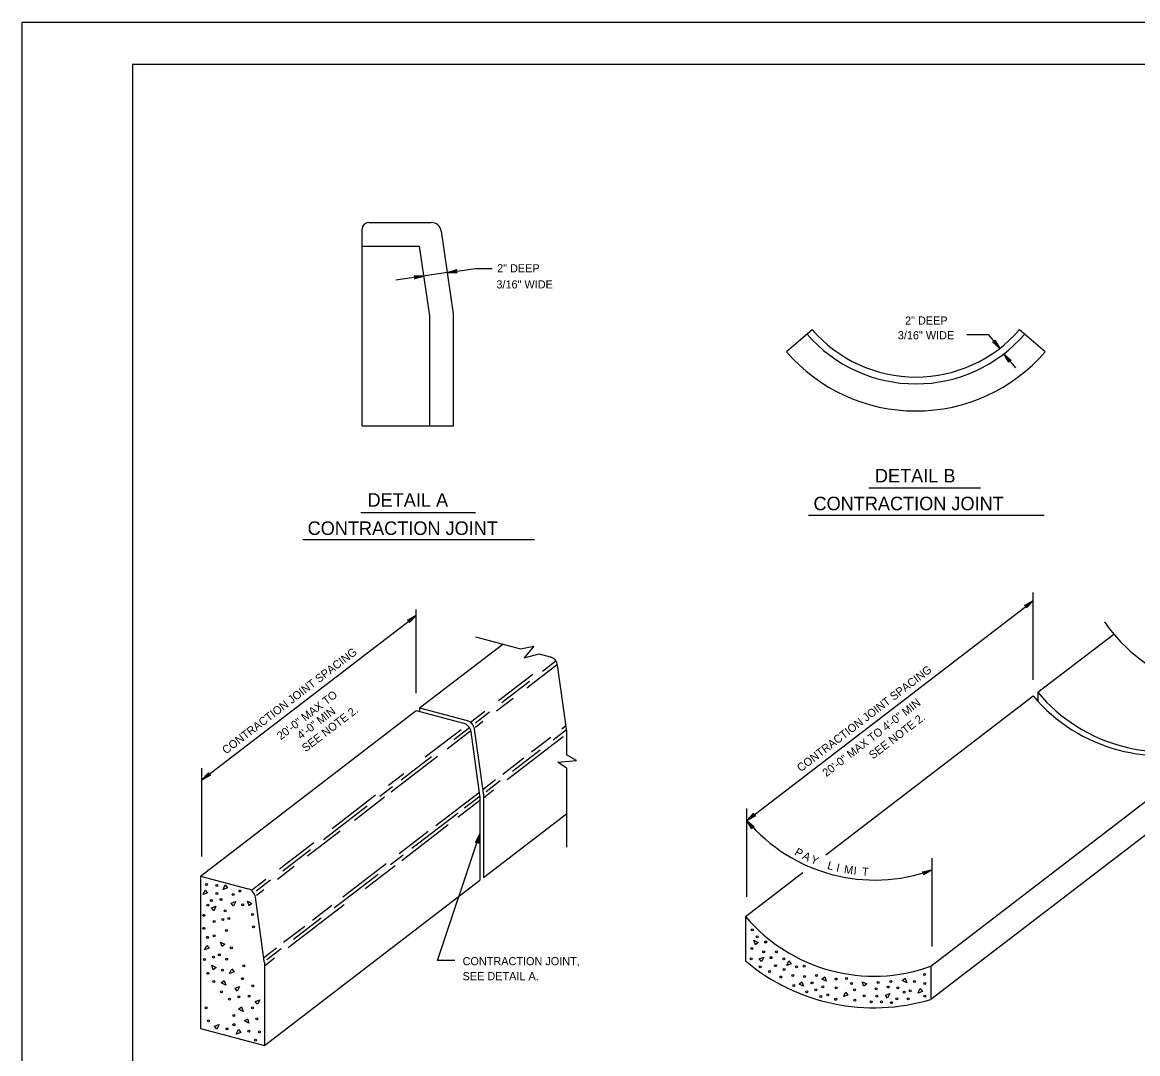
# Model space of a CAD drawing. Extents: x 2092490 to 2102560, y 980575 to 982524.
# Drawn here: x 2096834 to 2098130, y 981325 to 982524 of the extents above; entities that cross this region are included whole.
import ezdxf

# ---------------------------------------------------------------- set-up
doc = ezdxf.new("R2010")
doc.units = 0
for name, color, linetype in [('1', 7, 'Continuous'), ('2', 7, 'Continuous'), ('3', 7, 'Continuous'), ('57', 7, 'Continuous'), ('PLT-BNDY', 7, 'Continuous')]:
    doc.layers.add(name, color=color, linetype=linetype)

msp = doc.modelspace()

# ---------------------------------------------------------------- linework, layer by layer
at = {"layer": '1'}
for p, q in [((2099540.8, 982474.5), (2096962.1, 982474.5)), ((2096962.1, 982474.5), (2096962.1, 980624.1)), ((2097752, 982166.4), (2097722.2, 982140.7)), ((2098022.9, 982140.7), (2097993.1, 982166.4))]:
    msp.add_line(p, q, dxfattribs=at)
for radius in [167.3, 159.4, 198.8]:
    msp.add_arc((2097872.6, 982270.8), radius, 220.8681, 319.1319, dxfattribs=at)
at = {"layer": '2'}
for p, q in [((2097236.9, 982291), (2097309.4, 982291)), ((2097229, 982054.8), (2097229, 982283.2)), ((2097335.3, 982184.7), (2097321.1, 982281)), ((2097229, 982263.5), (2097295.8, 982263.5)), ((2097307.8, 982182.7), (2097295.8, 982263.5)), ((2097335.3, 982054.8), (2097335.3, 982184.7)), ((2097307.8, 982054.8), (2097307.8, 982182.7)), ((2097229, 982054.8), (2097335.3, 982054.8)), ((2097360.7, 981809.5), (2097413, 981795.5)), ((2098014.2, 981745), (2098102.5, 981812.7)), ((2097295.8, 981726.9), (2097392.4, 981801)), ((2097413, 981795.5), (2097428.7, 981798.5)), ((2097428.7, 981798.5), (2097417.5, 981785.1)), ((2097417.5, 981785.1), (2097434.7, 981789.6)), ((2097434.7, 981789.6), (2097447.5, 981786.2)), ((2097438.7, 981769.4), (2097454.3, 981781.4)), ((2097420.3, 981750.3), (2097456, 981777.7)), ((2097466.4, 981702.2), (2097456.2, 981776.4)), ((2097387.5, 981735.3), (2097427.5, 981766)), ((2097391.3, 981733.1), (2097423.6, 981757.9)), ((2098014.2, 981745), (2098014.2, 981734.8)), ((2097385.3, 981723.4), (2097404.6, 981738.2)), ((2097768, 981556.1), (2098008.8, 981740.9)), ((2097041.2, 981531.5), (2097291.8, 981723.8)), ((2097291.8, 981723.8), (2097347, 981709)), ((2097295.8, 981726.9), (2097351, 981712.1)), ((2097295.8, 981726.9), (2097295.8, 981722.7)), ((2097354.9, 981710.3), (2097371.7, 981723.1)), ((2097360.6, 981709.5), (2097377.1, 981722.2)), ((2097890.1, 981388.2), (2098317.9, 981716.5)), ((2097335.5, 981690.3), (2097353.7, 981704.2)), ((2097360.7, 981704.5), (2097369.5, 981711.3)), ((2097461.2, 981702.7), (2097465.9, 981706.3)), ((2097302.4, 981670), (2097344.1, 981701.9)), ((2097327.9, 981679.4), (2097355.4, 981700.5)), ((2097365.9, 981625), (2097355.6, 981699.2)), ((2097369.9, 981628.1), (2097359.6, 981702.3)), ((2097397.7, 981643.8), (2097462.8, 981693.7)), ((2097426, 981675.7), (2097448.5, 981692.9)), ((2097451.1, 981689.9), (2097466.5, 981701.7)), ((2097466.6, 981700.6), (2097466.6, 981672.5)), ((2097403.8, 981653.5), (2097436, 981678.3)), ((2097890.1, 981426.8), (2098224.2, 981683.2)), ((2097262.6, 981629.2), (2097316.7, 981670.8)), ((2097274.4, 981643.4), (2097309.7, 981670.5)), ((2097392.4, 981649.9), (2097416.9, 981668.7)), ((2097456.3, 981663.8), (2097478.1, 981665.8)), ((2097478.1, 981665.8), (2097466.6, 981672.5)), ((2097466.6, 981656.8), (2097456.3, 981663.8)), ((2097466.6, 981656.8), (2097466.6, 981565.2)), ((2097259.6, 981637.2), (2097277.4, 981650.8)), ((2097369.3, 981632.2), (2097384.1, 981643.5)), ((2097373, 981629.9), (2097389.6, 981642.6)), ((2097194.1, 981586.9), (2097244.7, 981625.7)), ((2097249.7, 981624.4), (2097264.2, 981635.6)), ((2097314.8, 981590.4), (2097365.3, 981629.1)), ((2097370, 981622.5), (2097381.9, 981631.7)), ((2097370, 981626.5), (2097370, 981529.8)), ((2097184.1, 981574.1), (2097235, 981613.2)), ((2097220, 981596.6), (2097255, 981623.4)), ((2097340.3, 981599.8), (2097366, 981619.5)), ((2097347.9, 981610.7), (2097366.1, 981624.6)), ((2097366, 981623.4), (2097366, 981526.8)), ((2097286.9, 981563.8), (2097340.6, 981605.1)), ((2097370, 981529.8), (2097466.6, 981603.9)), ((2097275, 981549.6), (2097329.2, 981591.2)), ((2097041.2, 981531.5), (2097107.8, 981582.5)), ((2097165.7, 981554.9), (2097203.5, 981583.9)), ((2097272.1, 981557.6), (2097305.8, 981583.5)), ((2097132.9, 981539.9), (2097172.9, 981570.6)), ((2097136.7, 981537.7), (2097169, 981562.5)), ((2097262.1, 981544.8), (2097276.7, 981556)), ((2097130.7, 981528), (2097150, 981542.9)), ((2097206.6, 981507.3), (2097257.1, 981546.1)), ((2097232.4, 981517), (2097267.4, 981543.8)), ((2097674.7, 981484.5), (2097741.2, 981535.5)), ((2097041.2, 981531.5), (2097041.2, 981354.3)), ((2097041.2, 981531.5), (2097096.4, 981516.7)), ((2097100.3, 981514.9), (2097117.1, 981527.8)), ((2097106, 981514.2), (2097122.5, 981526.9)), ((2097115.4, 981334.5), (2097366, 981526.8)), ((2097196.5, 981494.5), (2097247.5, 981533.6)), ((2097106.1, 981509.1), (2097114.9, 981515.9)), ((2097115.3, 981432.7), (2097105, 981506.9)), ((2097143.1, 981448.5), (2097208.2, 981498.4)), ((2097171.4, 981480.3), (2097193.9, 981497.6)), ((2097149.2, 981458.1), (2097181.4, 981482.9)), ((2097674.7, 981484.5), (2097674.7, 981432.9)), ((2097137.8, 981454.5), (2097162.3, 981473.3)), ((2097114.7, 981436.8), (2097129.5, 981448.2)), ((2097118.4, 981434.6), (2097135, 981447.3)), ((2097115.4, 981427.2), (2097127.3, 981436.3)), ((2097115.4, 981431.1), (2097115.4, 981334.5)), ((2097890.1, 981426.8), (2097890.1, 981388.2)), ((2097041.2, 981354.3), (2097115.4, 981334.5))]:
    msp.add_line(p, q, dxfattribs=at)
for centre, radius, start, end in [((2097236.9, 982283.2), 7.87, 90, 180), ((2097309.4, 982279.2), 11.8, 8.4289, 90), ((2098251.5, 981938), 194.6, 214.8148, 250.4307), ((2097444.5, 981774.8), 11.8, 7.8856, 75.0011), ((2098163.2, 981870.2), 194.6, 220.0465, 289.9543), ((2098157.8, 981866.1), 194.6, 220.0478, 289.9543), ((2097343.9, 981697.6), 11.8, 7.8856, 75.0011), ((2097347.9, 981700.7), 11.8, 7.8856, 75.0011), ((2097454.8, 981700.6), 11.8, 0, 7.8855), ((2097358.2, 981626.5), 11.8, 0, 7.8855), ((2097354.2, 981623.4), 11.8, 0, 7.8855), ((2097093.3, 981505.3), 11.8, 7.8856, 75.0011), ((2097823.7, 981609.7), 194.6, 220.0465, 289.9543), ((2097103.6, 981431.1), 11.8, 0, 7.8855), ((2097823.7, 981609.7), 231.3, 229.8893, 286.6912)]:
    msp.add_arc(centre, radius, start, end, dxfattribs=at)
at = {"layer": '3'}
for p, q in [((2097328.2, 982232.9), (2097360.7, 982237.7)), ((2097360.7, 982237.7), (2097380.2, 982237.7)), ((2097328.2, 982232.9), (2097268.3, 982224)), ((2097931.8, 982160.8), (2097956.8, 982160.8)), ((2097956.8, 982160.8), (2097970, 982144.6)), ((2097975, 982138.4), (2097988.3, 982122.1)), ((2097817.9, 981982.5), (2097947.7, 981982.5)), ((2097227.7, 981954), (2097360.9, 981954)), ((2097747.7, 981951), (2098021.6, 981951)), ((2097160.2, 981922.5), (2097429.3, 981922.5)), ((2098008.8, 981759.7), (2098008.8, 981861.2)), ((2097676.1, 981596.2), (2098008.8, 981851.5)), ((2097042.7, 981643.2), (2097291.8, 981834.4)), ((2097291.8, 981744), (2097291.8, 981841.3)), ((2097042.7, 981554.3), (2097042.7, 981657)), ((2097676.1, 981507.3), (2097676.1, 981610)), ((2097316.5, 981433.2), (2097366, 981580.6)), ((2097891.5, 981449.6), (2097891.5, 981552.2)), ((2097336.7, 981433.2), (2097316.5, 981433.2))]:
    msp.add_line(p, q, dxfattribs=at)
for points in [[(2097339, 982233.1), (2097338.5, 982233.8), (2097328.2, 982232.9), (2097339, 982233.1), (2097339.6, 982232.7), (2097328.2, 982232.9), (2097338.3, 982234.9), (2097338.6, 982235.7), (2097328.2, 982232.9), (2097339.1, 982236.3), (2097338.6, 982235.7)], [(2097290.1, 982228.6), (2097290.6, 982227.9), (2097300.9, 982228.8), (2097290.1, 982228.6), (2097289.5, 982229), (2097300.9, 982228.8), (2097290.8, 982226.8), (2097290.5, 982226), (2097300.9, 982228.8), (2097290, 982225.4), (2097290.5, 982226)], [(2097964.3, 982153.7), (2097963.9, 982152.9), (2097970, 982144.6), (2097964.3, 982153.7), (2097964.3, 982154.4), (2097970, 982144.6), (2097963.1, 982152.2), (2097962.2, 982152), (2097970, 982144.6), (2097961.5, 982152.2), (2097962.2, 982152)], [(2097980.7, 982129.3), (2097981, 982130.1), (2097975, 982138.4), (2097980.7, 982129.3), (2097980.7, 982128.6), (2097975, 982138.4), (2097981.9, 982130.8), (2097982.7, 982131), (2097975, 982138.4), (2097983.5, 982130.8), (2097982.7, 982131)], [(2097999.5, 981846), (2098000.3, 981845.6), (2098008.8, 981851.5), (2097999.5, 981846), (2097998.8, 981846), (2098008.8, 981851.5), (2098001, 981844.8), (2098001.1, 981843.9), (2098008.8, 981851.5), (2098001, 981843.2), (2098001.1, 981843.9)], [(2097282.5, 981828.9), (2097283.3, 981828.5), (2097291.8, 981834.4), (2097282.5, 981828.9), (2097281.8, 981829), (2097291.8, 981834.4), (2097284, 981827.7), (2097284.1, 981826.8), (2097291.8, 981834.4), (2097284, 981826.1), (2097284.1, 981826.8)], [(2097052, 981648.6), (2097051.2, 981649), (2097042.7, 981643.2), (2097052, 981648.6), (2097052.7, 981648.6), (2097042.7, 981643.2), (2097050.5, 981649.9), (2097050.4, 981650.7), (2097042.7, 981643.2), (2097050.5, 981651.5), (2097050.4, 981650.7)], [(2097685.5, 981601.6), (2097684.7, 981602), (2097676.1, 981596.2), (2097685.5, 981601.6), (2097686.2, 981601.6), (2097676.1, 981596.2), (2097684, 981602.9), (2097683.8, 981603.7), (2097676.1, 981596.2), (2097684, 981604.5), (2097683.8, 981603.7)], [(2097682, 981587.1), (2097682.3, 981587.9), (2097676.1, 981596.2), (2097682, 981587.1), (2097682, 981586.4), (2097676.1, 981596.2), (2097683.2, 981588.6), (2097684, 981588.8), (2097676.1, 981596.2), (2097684.8, 981588.7), (2097684, 981588.8)], [(2097361.3, 981570.9), (2097362.2, 981571), (2097366, 981580.6), (2097361.3, 981570.9), (2097360.7, 981570.5), (2097366, 981580.6), (2097363.2, 981570.7), (2097363.8, 981570.1), (2097366, 981580.6), (2097364.1, 981569.4), (2097363.8, 981570.1)], [(2097881, 981536.1), (2097881.6, 981535.5), (2097891.5, 981538.5), (2097881, 981536.1), (2097880.3, 981536.3), (2097891.5, 981538.5), (2097882, 981534.5), (2097881.9, 981533.6), (2097891.5, 981538.5), (2097881.6, 981532.9), (2097881.9, 981533.6)]]:
    msp.add_lwpolyline(points, dxfattribs=at)
msp.add_arc((2097825.1, 981721.4), 194.6, 220.0465, 289.9543, dxfattribs=at)
at = {"layer": '57'}
for points in [[(2097046.8, 981515.2), (2097049.4, 981511.8), (2097044.2, 981509.9)], [(2097070, 981521.2), (2097072.7, 981517.8), (2097067.4, 981516)], [(2097056.5, 981491.2), (2097053.9, 981494.5), (2097059.2, 981496.4)], [(2097079.7, 981496.4), (2097077, 981499.8), (2097082.3, 981501.7)], [(2097101, 981499.7), (2097097.6, 981497), (2097095.7, 981502.3)], [(2097048.7, 981450.9), (2097051.3, 981447.6), (2097046, 981445.7)], [(2097069.6, 981452.2), (2097066.2, 981449.5), (2097064.3, 981454.8)], [(2097689.4, 981454.2), (2097686.1, 981451.6), (2097684.2, 981456.8)], [(2097693.1, 981432), (2097690.5, 981435.4), (2097695.7, 981437.3)], [(2097725.1, 981432.8), (2097727.8, 981429.4), (2097722.5, 981427.5)], [(2097059.5, 981425.1), (2097056.1, 981422.5), (2097054.2, 981427.7)], [(2097077.5, 981423.5), (2097080.2, 981420.2), (2097074.9, 981418.3)], [(2097065.2, 981407.4), (2097068.6, 981410.1), (2097070.5, 981404.8)], [(2097736.9, 981405.9), (2097740.2, 981408.6), (2097742.1, 981403.3)], [(2097763.2, 981411.7), (2097766.6, 981414.3), (2097768.4, 981409.1)], [(2097815.5, 981406), (2097812.1, 981403.4), (2097810.2, 981408.6)], [(2097856.7, 981410), (2097860.1, 981412.6), (2097861.9, 981407.3)], [(2097083.9, 981397.7), (2097081.3, 981401.1), (2097086.6, 981403)], [(2097791.1, 981396.5), (2097793.7, 981393.2), (2097788.4, 981391.3)], [(2097839.8, 981389.6), (2097837.2, 981393), (2097842.5, 981394.8)], [(2097877.6, 981400.6), (2097880.3, 981397.2), (2097875, 981395.3)], [(2097085.5, 981376.7), (2097088.9, 981379.3), (2097090.7, 981374.1)], [(2097107.5, 981382.4), (2097104.9, 981385.7), (2097110.2, 981387.6)], [(2097060.1, 981353.6), (2097057.5, 981357), (2097062.7, 981358.8)], [(2097092.3, 981363.1), (2097095.7, 981365.7), (2097097.5, 981360.5)], [(2097085.5, 981353.1), (2097088.1, 981349.7), (2097082.8, 981347.8)]]:
    msp.add_lwpolyline(points, close=True, dxfattribs=at)
for centre in [(2097048.1, 981521.5), (2097060.1, 981520.5), (2097060.1, 981511.2), (2097079.3, 981510), (2097086.8, 981514.1), (2097049.7, 981497.5), (2097053.8, 981503.2), (2097065, 981504.3), (2097090.2, 981497.9), (2097045, 981485.8), (2097069.9, 981491.1), (2097074, 981482.1), (2097101.6, 981486.9), (2097045, 981470.7), (2097057.1, 981478.7), (2097067.1, 981480.8), (2097102.8, 981472.3), (2097682.5, 981469.1), (2097049.3, 981460.2), (2097057.1, 981462.1), (2097071.3, 981468.1), (2097688, 981460.9), (2097077, 981448.1), (2097681.9, 981447.3), (2097695.7, 981443.3), (2097698, 981454.8), (2097710.6, 981443.3), (2097045.7, 981434.5), (2097056.2, 981437.1), (2097063.1, 981439.8), (2097071.6, 981434.9), (2097681.3, 981435.3), (2097704.2, 981436.6), (2097719.2, 981435.3), (2097049.7, 981418.4), (2097066.9, 981422.1), (2097091.7, 981427), (2097691.7, 981426.1), (2097702.6, 981420.4), (2097709.4, 981427.3), (2097719.6, 981422.8), (2097733.7, 981426), (2097742.7, 981426.7), (2097882.6, 981416.9), (2097056.7, 981408.9), (2097089.9, 981412.2), (2097101.9, 981404), (2097715.7, 981414.1), (2097729.5, 981415.8), (2097730.6, 981404.3), (2097743.3, 981414.6), (2097751.9, 981407.2), (2097757, 981415.8), (2097779.9, 981411.8), (2097792, 981412.3), (2097797.7, 981406.6), (2097828.7, 981407.7), (2097843.6, 981408.9), (2097871.1, 981408.9), (2097883.1, 981406.6), (2097065.5, 981396.8), (2097085.8, 981391.1), (2097097.9, 981391.9), (2097745.9, 981396.9), (2097756.4, 981399.1), (2097762.1, 981391.6), (2097764.5, 981402.6), (2097770.2, 981393.4), (2097779.9, 981401.4), (2097801.2, 981399.1), (2097812.6, 981392.3), (2097826.4, 981400.3), (2097827.3, 981392), (2097840.3, 981402.5), (2097851.6, 981401.4), (2097858.9, 981396.4), (2097865.9, 981398), (2097883.1, 981391.7), (2097047.7, 981378.3), (2097074.8, 981388.5), (2097101.6, 981378.3), (2097779.4, 981388.2), (2097801.7, 981387.1), (2097820.6, 981385.4), (2097832.7, 981385.4), (2097844.3, 981384.3), (2097850.5, 981388.8), (2097863.6, 981388.8), (2097079.9, 981369.3), (2097106.8, 981365.5), (2097050.5, 981363.3), (2097072, 981354), (2097080.1, 981358.7), (2097097.4, 981351.1), (2097105.2, 981340.8), (2097109.8, 981350.4)]:
    msp.add_circle(centre, 1.14, dxfattribs=at)
at = {"layer": 'PLT-BNDY'}
msp.add_lwpolyline([(2096834.1, 982523.7), (2099593.3, 982523.7), (2099593.3, 980574.9), (2096834.1, 980574.9)], close=True, dxfattribs=at)

# ---------------------------------------------------------------- texts
at = {"layer": '3'}
for s, height, p in [('2" DEEP', 9.45, (2097385.9, 982233.1)), ('3/16" WIDE', 9.45, (2097385.1, 982214.4)), ('2" DEEP', 9.45, (2097860, 982172.4)), ('3/16" WIDE', 9.45, (2097851.6, 982155.3)), ('DETAIL B', 15.75, (2097825, 981988.9)), ('DETAIL A', 15.75, (2097235.3, 981960.7)), ('CONTRACTION JOINT', 15.748, (2097753.6, 981956.6)), ('CONTRACTION JOINT', 15.748, (2097165.7, 981927.9)), ('CONTRACTION JOINT,', 9.449, (2097345.8, 981427.8)), ('SEE DETAIL A.', 9.449, (2097345.8, 981410.4))]:
    msp.add_text(s, height=height, dxfattribs=at).set_placement(p)
for s, height, rotation, p in [('CONTRACTION JOINT SPACING', 9.449, 37.5002, (2097070.9, 981672.6)), ('CONTRACTION JOINT SPACING', 9.449, 37.5002, (2097738.9, 981652)), ('20\'-0" MAX TO', 9.449, 37.5002, (2097134.5, 981689.1)), ('20\'-0" MAX TO 4\'-0" MIN', 9.449, 37.5002, (2097768.5, 981646.2)), ('4\'-0" MIN', 9.45, 37.5002, (2097158, 981689.8)), ('SEE NOTE 2.', 9.449, 37.5002, (2097163.5, 981675.2)), ('SEE NOTE 2.', 9.449, 37.5002, (2097822.5, 981666.7)), ('P', 9.45, 329.6864, (2097730.7, 981556.7)), ('A', 9.45, 333.2573, (2097739.8, 981551.9)), ('Y', 9.45, 336.8282, (2097749.3, 981547.4)), ('L', 9.45, 343.97, (2097769, 981540)), ('I', 9.45, 347.5409, (2097779.5, 981537.1)), ('M', 9.45, 351.1118, (2097788.6, 981535)), ('I', 9.45, 354.6827, (2097799.9, 981533.1)), ('T', 9.45, 354.6827, (2097809.6, 981532.2))]:
    msp.add_text(s, height=height, rotation=rotation, dxfattribs=at).set_placement(p)

doc.saveas('drawing.dxf')
